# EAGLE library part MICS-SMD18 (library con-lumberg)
CONNECTOR
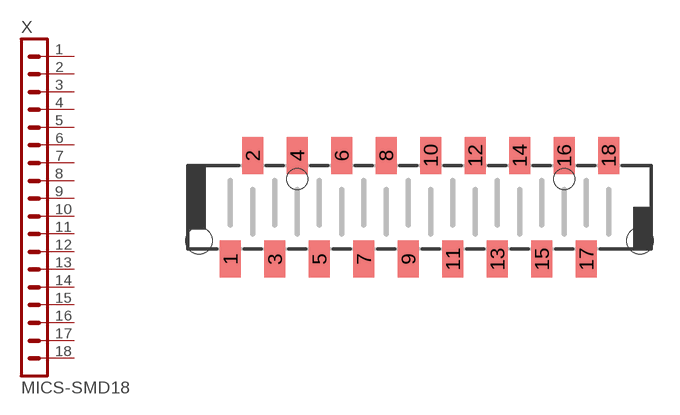
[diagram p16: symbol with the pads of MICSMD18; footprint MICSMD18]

Designator prefix X

## MICS-SMD18 (OC_FARNELL: unknown; OC_NEWARK: unknown)  [MICSMD18]
1  1  pas
2  2  pas
3  3  pas
4  4  pas
5  5  pas
6  6  pas
7  7  pas
8  8  pas
9  9  pas
10  10  pas
11  11  pas
12  12  pas
13  13  pas
14  14  pas
15  15  pas
16  16  pas
17  17  pas
18  18  pas

## Footprint MICSMD18 (pad centres in mm)
CONNECTOR
smd 1.2 x 2.1: 1 -10.795,-2.959; 2 -9.525,2.959; 3 -8.255,-2.959; 4 -6.985,2.959; 5 -5.715,-2.959; 6 -4.445,2.959; 7 -3.175,-2.959; 8 -1.905,2.959; 9 -0.635,-2.959; 10 0.635,2.959; 11 1.905,-2.959; 12 3.175,2.959; 13 4.445,-2.959; 14 5.715,2.959; 15 6.985,-2.959; 16 8.255,2.959; 17 9.525,-2.959; 18 10.795,2.959
hole 1.5 at 12.595,-1.912
hole 1.5 at -12.595,-1.912
hole 1.2 at -6.985,1.6
hole 1.2 at 8.255,1.6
